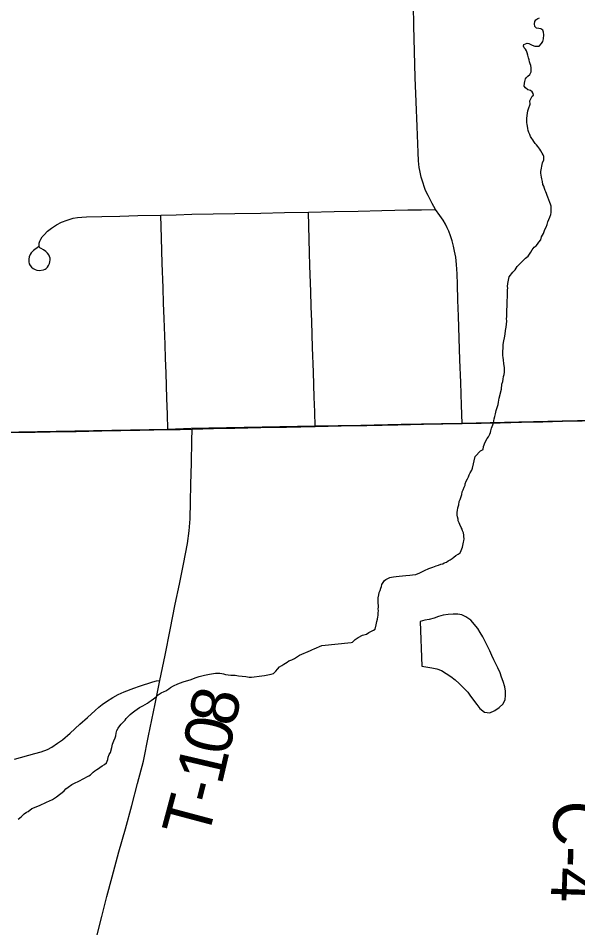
# Model space of a CAD drawing. Extents: x 103424 to 290657, y 38711 to 110967.
# Drawn here: x 130397 to 133964, y 93661 to 99466 of the extents above; entities that cross this region are included whole.
import ezdxf

# ---------------------------------------------------------------- set-up
doc = ezdxf.new("R2010")
doc.units = 0
for name, color, linetype in [('GM_X_Corporation', 7, 'Continuous'), ('GM_X_County_Road', 7, 'Continuous'), ('GM_X_County_Road_Text', 7, 'Continuous'), ('GM_X_Minor_Lake', 7, 'Continuous'), ('GM_X_Minor_River', 7, 'Continuous'), ('GM_X_Township_Road', 7, 'Continuous'), ('GM_X_Township_Road_Text', 7, 'Continuous')]:
    doc.layers.add(name, color=color, linetype=linetype)

msp = doc.modelspace()

# ---------------------------------------------------------------- linework, layer by layer
at = {"layer": 'GM_X_Corporation'}
for points in [[(148354.5, 110967.2), (119699, 110967.2), (119716.9, 106542.5), (119719.8, 106322.8), (119720.8, 106006.3), (119709.7, 99445.7), (119706.4, 99064.2), (119663.9, 96690), (127752.9, 96778.3), (127904.6, 96781), (127960.9, 96782.1), (128017.2, 96783.1), (128144.7, 96785.8), (131350.5, 96844.5), (131500.4, 96848.9), (132289.6, 96863.9), (132581, 96869.6), (132838, 96874.6), (133225.9, 96882.3), (133496.3, 96888.5), (133864.7, 96896.9), (134160.1, 96903.7)], [(119639, 84504.6), (119641.6, 85722.3), (119634.5, 87732.9), (119633.9, 87813.5), (119633.9, 87824), (119641.1, 89532.2), (119665, 94023.8), (119663.9, 96690), (127752.9, 96778.3), (127904.6, 96781), (127960.9, 96782.1), (128017.2, 96783.1), (128144.7, 96785.8), (131350.5, 96844.5), (131500.4, 96848.9), (132289.6, 96863.9), (132581, 96869.6), (132838, 96874.6), (133225.9, 96882.3), (133496.3, 96888.5), (133864.7, 96896.9), (134160.1, 96903.7)]]:
    msp.add_lwpolyline(points, dxfattribs=at)
at = {"layer": 'GM_X_County_Road'}
for points in [[(131505.2, 96843.9), (131641.5, 96846.8), (131777.8, 96849.7), (131942.9, 96853.1), (132107.9, 96856.5), (132199, 96858.4), (132290.1, 96860.3), (132455.2, 96863.7), (132620.2, 96867.2), (132718.2, 96869.2), (132816.2, 96871.2), (132981.2, 96874.7), (133104.4, 96877.2), (133227.6, 96879.8), (133348, 96882.2), (133468.5, 96884.8), (133605.4, 96887.9), (133742.2, 96891.1), (133867.5, 96893.9), (133992.7, 96896.8), (134118.4, 96899.6), (134244.1, 96902.4), (134337.3, 96904.4), (134430.5, 96906.5)], [(130244.3, 96820.3), (130409.4, 96823.3), (130505.1, 96825.1), (130600.8, 96826.8), (130765.9, 96829.6), (130930.9, 96832.3), (131051.8, 96834.3), (131172.6, 96836.4), (131261.7, 96838.4), (131350.9, 96840.5), (131428.7, 96842.2), (131505.2, 96843.9)], [(131300.2, 95240.2), (131332.9, 95402), (131365.6, 95563.8), (131398.2, 95725.6), (131424.2, 95854.1), (131450.2, 95982.6), (131476.8, 96114.1), (131486.4, 96194), (131492.8, 96270.9), (131495.3, 96380.2), (131497.7, 96489.6), (131500.7, 96628.8), (131503.8, 96768.1), (131505.2, 96843.9)], [(130372.3, 94737.2), (130502.2, 94773.2), (130543.2, 94784.7), (130583.2, 94799.1), (130611.9, 94814.1), (130647.7, 94838.8), (130679.1, 94861), (130727.9, 94903.2), (130789.8, 94960.1), (130838.3, 95003.7), (130888.2, 95048.8), (130910.5, 95068.8), (130933, 95086.3), (130958.9, 95105.5), (131000, 95132), (131035.1, 95150.4), (131072.7, 95167.5), (131133.1, 95190.4), (131169.8, 95203.3), (131255.1, 95230.7), (131277.7, 95237.9), (131300.2, 95240.2)]]:
    msp.add_lwpolyline(points, dxfattribs=at)
at = {"layer": 'GM_X_Minor_Lake'}
msp.add_line((132959, 95616.8), (132970.3, 95331.6), dxfattribs=at)
msp.add_lwpolyline([(132970.3, 95331.6), (133034.4, 95320.1), (133066.7, 95314.2), (133095, 95302.2), (133125.4, 95284.1), (133155.7, 95264), (133182, 95243.9), (133208.3, 95219.8), (133236.6, 95193.6), (133262.9, 95165.4), (133281.2, 95139.2), (133321.7, 95086.8), (133339.9, 95060.6), (133370.3, 95036.5), (133402.6, 95032.6), (133434.8, 95048.9), (133463, 95067.1), (133489.2, 95091.5), (133501.3, 95117.8), (133503.2, 95144), (133503.1, 95170.3), (133499, 95198.5), (133488.8, 95232.8), (133478.7, 95261.1), (133468.5, 95287.3), (133454.3, 95319.6), (133429.9, 95372), (133415.7, 95398.2), (133403.5, 95428.5), (133358.9, 95517.2), (133342.7, 95545.4), (133326.4, 95571.6), (133281.9, 95624), (133251.6, 95646.1), (133225.3, 95658.1), (133199, 95662), (133170.8, 95661.9), (133138.5, 95659.8), (133106.2, 95655.7), (133075.9, 95647.5), (133047.7, 95637.3), (133017.4, 95629.1), (132989.2, 95625), (132959, 95616.8)], dxfattribs=at)
at = {"layer": 'GM_X_Minor_River'}
for points in [[(133739.3, 98423.7), (133734.9, 98441.8), (133732.7, 98451.8), (133730.5, 98463.9), (133728.2, 98478), (133728, 98488.1), (133739.1, 98542.9), (133748.9, 98563.2), (133748.5, 98583.4), (133744.3, 98593.5), (133738, 98605.5), (133729.7, 98619.5), (133721.4, 98631.4), (133709, 98647.4), (133700.8, 98657.3), (133692.5, 98667.3), (133684.2, 98679.3), (133678, 98689.2), (133671.8, 98699.2), (133663.5, 98711.2), (133659.2, 98723.3), (133652.9, 98737.3), (133648.7, 98749.3), (133646.4, 98761.4), (133644.1, 98777.5), (133641.9, 98787.6), (133639.7, 98799.7), (133639.5, 98811.8), (133639.2, 98825.9), (133640.9, 98846.2), (133644.7, 98860.4), (133646.4, 98874.5), (133650.2, 98888.8), (133659.8, 98917.2), (133659.4, 98939.4), (133673, 98967.9), (133683, 98974.2), (133680.7, 98986.3), (133672.5, 98996.2), (133662.3, 99004.1), (133646, 99009.9), (133631.7, 99021.8), (133623.4, 99031.7), (133625.1, 99051.9), (133626.9, 99062.1), (133630.7, 99078.3), (133636.5, 99088.5), (133646.5, 99096.8), (133658.4, 99107.1), (133666.2, 99123.4), (133668, 99135.5), (133667.7, 99149.7), (133665.4, 99163.8), (133661.2, 99175.8), (133656.9, 99187.9), (133654.7, 99200), (133650.4, 99214), (133646.1, 99230.1), (133641.8, 99244.2), (133637.5, 99258.2), (133631.3, 99268.2), (133623, 99278.2), (133618.8, 99288.2), (133620.6, 99298.3), (133640.7, 99306.8), (133652.8, 99305), (133673.2, 99295.2), (133691.5, 99287.5), (133707.6, 99287.8), (133717.7, 99287.9), (133733.5, 99304.4), (133741.4, 99316.7), (133745.1, 99334.9), (133748.7, 99359.2), (133746.4, 99377.4), (133742.1, 99389.4), (133727.8, 99399.2), (133715.7, 99401), (133701.5, 99402.8), (133691.2, 99412.7), (133688.9, 99430.9), (133690.7, 99445), (133696.5, 99455.2), (133710.5, 99463.6), (133720.5, 99467.8)], [(133288.1, 96581.1), (133293.9, 96595.3), (133310.7, 96668.4), (133344.4, 96705.3), (133360.4, 96713.7), (133364.1, 96732), (133373.6, 96760.4), (133387.3, 96784.9), (133395.2, 96795.2), (133403, 96811.5), (133406.8, 96821.6), (133410.7, 96833.8), (133414.4, 96850.1), (133422.1, 96870.4), (133425.9, 96884.6), (133431.5, 96908.9), (133435.2, 96925.2), (133439, 96941.4), (133444.7, 96961.7), (133450.4, 96982), (133456.1, 97000.3), (133459.8, 97016.5), (133463.4, 97040.8), (133478.5, 97099.7), (133480, 97130), (133485.7, 97148.3), (133489.5, 97162.5), (133491.2, 97178.7), (133495, 97192.9), (133496.8, 97207.1), (133496.5, 97221.3), (133496.2, 97237.4), (133493.8, 97259.6), (133491.3, 97285.8), (133489, 97299.9), (133486.8, 97314), (133486.3, 97340.3), (133488, 97360.5), (133489.5, 97384.8), (133493.2, 97407.1), (133496.9, 97427.3), (133500.5, 97449.6), (133504.1, 97473.9), (133507.8, 97494.2), (133509.4, 97514.4), (133511.1, 97532.7), (133510.8, 97548.8), (133512.6, 97561), (133512.4, 97575.1), (133512, 97593.3), (133511.7, 97609.4), (133513.5, 97623.6), (133513.3, 97637.8), (133515, 97651.9), (133514.8, 97666.1), (133516.4, 97684.3), (133516.2, 97700.4), (133515.9, 97714.6), (133515.6, 97732.7), (133517.4, 97742.9), (133517.2, 97753), (133518.9, 97773.2), (133526.2, 97815.8), (133549.9, 97846.5), (133565.7, 97860.9), (133577.5, 97881.3), (133603.2, 97908.1), (133631, 97934.8), (133646.9, 97947.2), (133664.6, 97973.8), (133674.4, 97988.1), (133686.3, 98004.5), (133698.2, 98012.8), (133708.1, 98025.1), (133715.9, 98037.4), (133727.8, 98051.7), (133733.5, 98070), (133745.2, 98092.5), (133754.9, 98116.9), (133762.6, 98133.2), (133768.4, 98149.4), (133774.1, 98167.7), (133779.9, 98182), (133785.7, 98196.2), (133791.5, 98212.5), (133795.3, 98226.7), (133795.1, 98238.8), (133794.8, 98250.9), (133794.5, 98267.1), (133790.3, 98279.1), (133786.1, 98289.2), (133779.7, 98307.2), (133773.4, 98323.3), (133769.1, 98335.3), (133764.9, 98347.4), (133760.6, 98357.4), (133756.4, 98367.4), (133752.2, 98379.5), (133747.9, 98393.5), (133741.6, 98405.5), (133739.3, 98423.7)], [(132332.5, 95462.1), (132518.8, 95482.3), (132528.9, 95484.5), (132544.7, 95500.9), (132564.7, 95513.4), (132592.7, 95528), (132616.8, 95534.5), (132632.7, 95544.9), (132648.7, 95555.3), (132662.7, 95561.6), (132672.7, 95567.9), (132678.2, 95594.2), (132683.9, 95616.6), (132687.7, 95630.8), (132689.4, 95645), (132691.3, 95655.1), (132691, 95671.3), (132692.8, 95683.4), (132692.5, 95697.5), (132694.4, 95707.7), (132691.7, 95744), (132691.5, 95754.1), (132691.3, 95766.2), (132695, 95786.5), (132698.7, 95800.7), (132704.6, 95812.9), (132708.3, 95829.2), (132712.2, 95839.3), (132716, 95851.5), (132723.8, 95865.8), (132731.7, 95878.1), (132741.6, 95884.3), (132753.6, 95890.6), (132765.6, 95896.9), (132777.7, 95899.1), (132789.8, 95901.3), (132805.9, 95903.6), (132826, 95906), (132846.2, 95906.4), (132868.3, 95908.8), (132894.5, 95911.3), (132910.6, 95913.6), (132932.8, 95916), (132956.8, 95926.6), (132986.8, 95941.2), (133014.8, 95953.9), (133040.9, 95962.4), (133060.9, 95970.9), (133077, 95975.2), (133091, 95981.5), (133103.1, 95983.8), (133113, 95990), (133127.1, 95994.3), (133137, 96002.5), (133151, 96008.9), (133163, 96017.1), (133174.9, 96027.5), (133186.9, 96037.8), (133200.8, 96046.1), (133214.8, 96054.5), (133220.6, 96068.7), (133224.4, 96078.9), (133228.3, 96091.1), (133233.9, 96111.4), (133235.8, 96121.5), (133237.6, 96131.6), (133239.4, 96143.8), (133237.2, 96157.9), (133237, 96168), (133234.7, 96182.1), (133228.4, 96194.1), (133226.2, 96204.2), (133220, 96216.2), (133211.6, 96234.2), (133207.3, 96246.3), (133201, 96258.3), (133200.9, 96268.4), (133196.5, 96284.5), (133194.3, 96294.5), (133196, 96312.7), (133197.8, 96324.9), (133199.6, 96341.1), (133205.2, 96361.4), (133208.9, 96381.7), (133214.7, 96393.9), (133220.4, 96414.2), (133224.3, 96426.4), (133228, 96442.6), (133233.8, 96456.9), (133239.6, 96473.1), (133245.4, 96485.4), (133247.2, 96495.5), (133253, 96511.8), (133260.8, 96526), (133266.6, 96538.3), (133272.4, 96552.5), (133278.3, 96564.7), (133288.1, 96581.1)], [(131192.1, 95076.8), (131206.1, 95087), (131220.2, 95095.2), (131232.2, 95103.4), (131244.2, 95111.6), (131258.3, 95121.9), (131278.3, 95138.2), (131288.2, 95148.4), (131308.3, 95160.7), (131326.4, 95169), (131338.5, 95173.2), (131356.5, 95185.5), (131368.5, 95195.7), (131386.6, 95206), (131414.7, 95218.4), (131448.9, 95230.8), (131499.2, 95245.5), (131525.3, 95255.8), (131551.5, 95264.2), (131583.7, 95272.6), (131616, 95279), (131642.2, 95283.3), (131654.2, 95285.4), (131666.4, 95285.5), (131682.5, 95285.7), (131694.7, 95283.8), (131704.8, 95281.9), (131719, 95278), (131735.2, 95276.1), (131753.4, 95274.3), (131779.6, 95272.5), (131801.9, 95268.7), (131824.1, 95266.9), (131848.4, 95265.1), (131868.6, 95261.3), (131884.8, 95261.4), (131900.9, 95263.6), (131933.2, 95268), (131967.5, 95272.4), (132009.8, 95280.9), (132023.9, 95285), (132039.9, 95299.3), (132049.8, 95311.6), (132061.8, 95325.8), (132077.8, 95336.1), (132089.8, 95344.3), (132101.9, 95350.5), (132111.9, 95356.6), (132121.9, 95364.8), (132142, 95371.1), (132158.1, 95379.3), (132170.1, 95387.5), (132190.2, 95401.9), (132260.5, 95430.9), (132272.6, 95437), (132282.6, 95441.2), (132332.5, 95462.1)], [(130396.7, 94353.6), (130414.7, 94369.9), (130434.6, 94388.3), (130450.7, 94398.6), (130460.7, 94402.7), (130482.7, 94423.2), (130533, 94441.8), (130577.2, 94462.5), (130615.4, 94481), (130641.4, 94497.5), (130659.4, 94511.8), (130677.5, 94524.1), (130689.4, 94536.3), (130701.4, 94548.6), (130715.4, 94558.8), (130739.5, 94575.2), (130759.6, 94585.5), (130779.7, 94593.8), (130791.7, 94602), (130805.7, 94610.2), (130819.8, 94616.4), (130833.8, 94624.6), (130847.9, 94630.9), (130857.9, 94637), (130873.9, 94655.4), (130885.9, 94663.6), (130897.9, 94671.8), (130907.9, 94677.9), (130918, 94684.1), (130932, 94694.3), (130948, 94702.6), (130960, 94714.8), (130967.9, 94735.1), (130969.7, 94749.3), (130977.6, 94767.5), (130985.5, 94779.7), (130993.2, 94812.1), (130997, 94832.4), (131006.9, 94854.7), (131014.7, 94872.9), (131018.6, 94887.1), (131020.4, 94903.3), (131026.3, 94919.5), (131034.2, 94935.8), (131044.1, 94950), (131054.1, 94960.2), (131066.1, 94974.5), (131078, 94986.7), (131086, 94996.9), (131096, 95007.1), (131110, 95021.4), (131124, 95033.6), (131140, 95045.9), (131156, 95056.2), (131170, 95066.4), (131182.1, 95072.6), (131192.1, 95076.8)]]:
    msp.add_lwpolyline(points, dxfattribs=at)
at = {"layer": 'GM_X_Township_Road'}
for points in [[(133227.6, 96879.8), (133223.2, 96996.2), (133217.8, 97140.9), (133212.3, 97285.7), (133208, 97424.9), (133203.7, 97564.2), (133200.1, 97665.7), (133196.6, 97767.2), (133194.6, 97835.4), (133191.3, 97895), (133186.1, 97940.8), (133179.3, 97979.1), (133172.3, 98012), (133162.5, 98046.1), (133152.7, 98077.1), (133142.6, 98106.1), (133132.4, 98128.8), (133121.3, 98151.8), (133106.2, 98177.1), (133085.4, 98208), (133057, 98246.1), (133036.1, 98282.8), (133009.5, 98335), (133000.5, 98353.9), (132992.2, 98373.1), (132984.4, 98392.6), (132977.6, 98412.4), (132971.3, 98432.4), (132965.8, 98452.6), (132961, 98473), (132957, 98493.6), (132953.8, 98514.2), (132951.2, 98535.1), (132949.5, 98555.9), (132945.7, 98609.7), (132939.8, 98774.6), (132934.2, 98931.6), (132928.6, 99088.6), (132924, 99253), (132919.5, 99417.4), (132916.8, 99549.4)], [(130526.5, 98006.3), (130494.5, 97983.5), (130480.1, 97969.5), (130472.4, 97957.6), (130466.8, 97943.6), (130464.4, 97929.2), (130464.8, 97911.9), (130467.5, 97899.2), (130473.8, 97887.3), (130481.6, 97877.4), (130491.6, 97869), (130504.1, 97861.8), (130515.2, 97857.9), (130529.5, 97856.3), (130557.1, 97859.3), (130567.8, 97863.7), (130575.6, 97869.7), (130583.6, 97877.3), (130590, 97887.3), (130595.6, 97899.9), (130599.1, 97911.2), (130600.6, 97923.8), (130600.2, 97935.2), (130597.3, 97946.2), (130591.7, 97956.9), (130584, 97967.3), (130573.8, 97978.2), (130558.6, 97987.9), (130543.1, 97996), (130535.7, 98001.2), (130530.2, 98009.2), (130529.8, 98020.3), (130531.3, 98031.4), (130535.7, 98044.3), (130541.3, 98057.1), (130549.8, 98070.6), (130561.6, 98084.3), (130583.6, 98107.6), (130609.2, 98127.2), (130640.1, 98147.9), (130672.6, 98164.1), (130708.4, 98177.8), (130747.2, 98189.6), (130774.8, 98194.5), (130802.8, 98197), (130831.2, 98198.4), (130930.5, 98200.5), (131044.5, 98203.4), (131158.5, 98206.3), (131306.4, 98209.3), (131404.6, 98212), (131502.9, 98214.7), (131640.7, 98217.1), (131778.5, 98219.6), (131943.6, 98223), (132095, 98226.1), (132246.5, 98229.2), (132411.5, 98232.6), (132563.4, 98235.7), (132715.2, 98238.9), (132880.3, 98242.4), (132968.6, 98244.2), (133057, 98246.1)], [(132290.1, 96860.3), (132287.2, 96953.9), (132284.1, 97047.4), (132278.6, 97206.4), (132273.2, 97365.4), (132268.1, 97530.4), (132265.1, 97626.1), (132262.2, 97721.7), (132257, 97886.7), (132254.4, 97970.7), (132251.9, 98054.6), (132249.2, 98141.9), (132246.5, 98229.2)], [(131350.9, 96840.5), (131347.8, 96939.6), (131344.8, 97038.7), (131339.7, 97203.7), (131336.9, 97293.7), (131334.2, 97383.7), (131327.8, 97548.7), (131323.9, 97646.6), (131320.1, 97744.5), (131315.4, 97903.2), (131310.8, 98061.9), (131306.4, 98209.3)], [(130889.9, 93572.7), (130930.5, 93732.6), (130962.8, 93860), (130995.1, 93987.3), (131039.1, 94146.4), (131079.9, 94293.8), (131120.6, 94441.3), (131158.1, 94582.8), (131195.5, 94724.4), (131228.3, 94886.2), (131249, 94988.6), (131269.8, 95091), (131300.2, 95240.2)]]:
    msp.add_lwpolyline(points, dxfattribs=at)

# ---------------------------------------------------------------- texts
at = {"layer": 'GM_X_County_Road_Text'}
msp.add_text('C-4', height=301.87, rotation=268.16641, dxfattribs=at).set_placement((133813.2, 94477))
at = {"layer": 'GM_X_Township_Road_Text'}
for s, rotation, p in [('8', 78.44241, (131776.7, 94937.4)), ('0', 77.91069, (131737.2, 94752.6)), ('1', 76.83411, (131693.5, 94565.5)), ('-', 75.78105, (131661.6, 94439.4)), ('T', 75.05422, (131602.3, 94217.2))]:
    msp.add_text(s, height=301.9, rotation=rotation, dxfattribs=at).set_placement(p)

doc.saveas('drawing.dxf')
